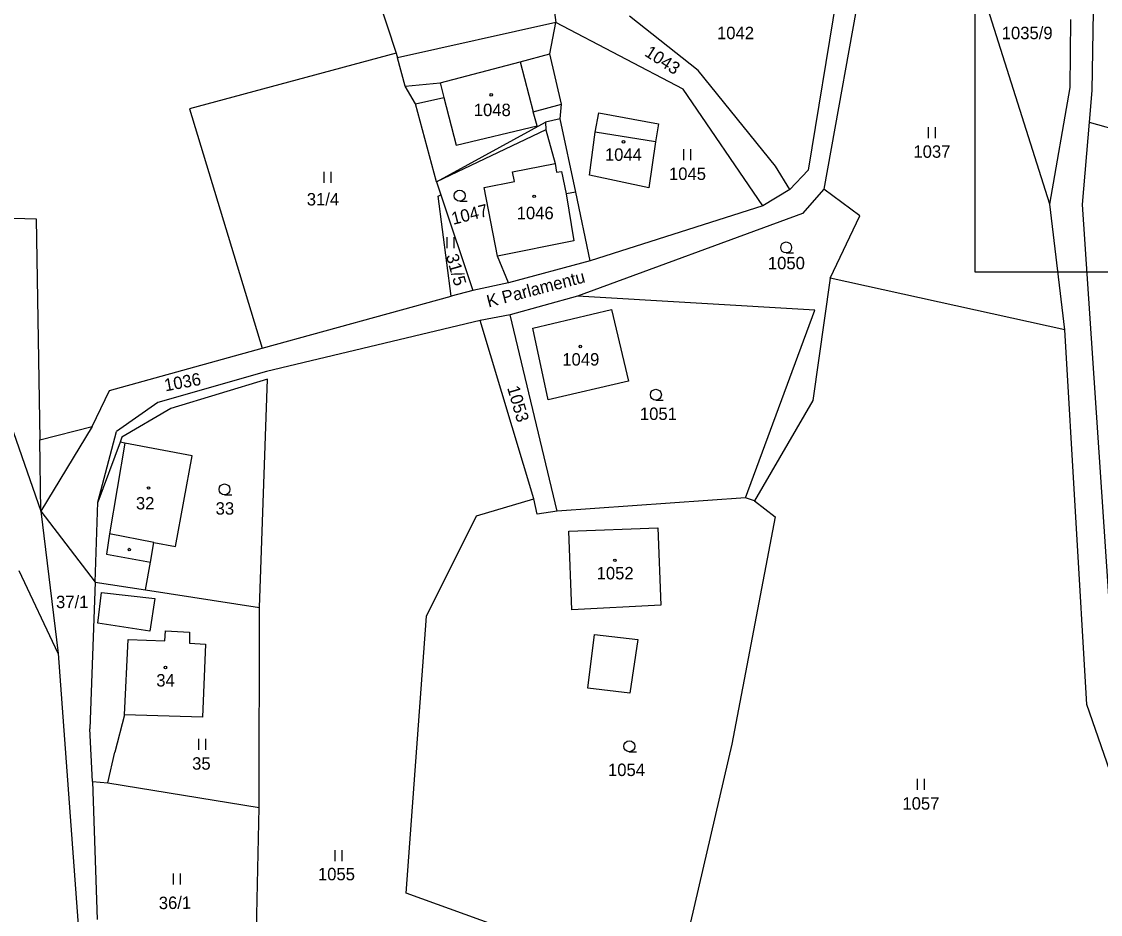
# Model space of a CAD drawing. Extents: x -670359 to -668019, y -978807 to -976674.
# Drawn here: x -670130.3 to -669982.9, y -977587.7 to -977465.8 of the extents above; entities that cross this region are included whole.
import ezdxf

# ---------------------------------------------------------------- set-up
doc = ezdxf.new("R2010")
doc.units = 0
for name, color, linetype in [('Hranice parcel', 7, 'Continuous'), ('ML1000', 7, 'Continuous'), ('Parcelní čísla', 7, 'Continuous'), ('Pop  PČ popisy', 7, 'Continuous'), ('Vnitřní kresba', 7, 'Continuous'), ('Značky budov', 7, 'Continuous'), ('Značky kultur', 7, 'Continuous')]:
    doc.layers.add(name, color=color, linetype=linetype)

msp = doc.modelspace()

# ---------------------------------------------------------------- linework, layer by layer
at = {"layer": 'Hranice parcel'}
for p, q in [((-670088.14, -977442.36), (-670079.11, -977470.1)), ((-670018.36, -977458.79), (-670022.83, -977486.05)), ((-669983.91, -977464.41), (-669984.06, -977475.2)), ((-669987.06, -977474.79), (-669986.93, -977465.5)), ((-669989.82, -977490.72), (-669987.06, -977474.79)), ((-669984.06, -977475.2), (-669984.43, -977479.49)), ((-669984.43, -977479.49), (-669985.41, -977490.75)), ((-669984.43, -977479.49), (-669976.06, -977481.88)), ((-670073, -977489.41), (-670068.64, -977502.48)), ((-670068.64, -977502.48), (-670071.6, -977503.29))]:
    msp.add_line(p, q, dxfattribs=at)
for points in [[(-670059.08, -977452.8), (-670057.31, -977465.91)], [(-670015.27, -977458.55), (-670020.69, -977488.66)], [(-669989.82, -977490.72), (-669999.13, -977461.22)], [(-670057.31, -977465.91), (-670078.9, -977470.74)], [(-670058.09, -977470.17), (-670057.31, -977465.91)], [(-670039.88, -977475.01), (-670057.31, -977465.91)], [(-670037.86, -977472.47), (-670047.21, -977465.04)], [(-670079.11, -977470.1), (-670107.35, -977477.66), (-670097.41, -977510.39)], [(-670079.11, -977470.1), (-670078.9, -977470.74)], [(-670077.89, -977474.59), (-670078.9, -977470.74)], [(-670056.54, -977477.05), (-670058.09, -977470.17)], [(-670027.27, -977485.52), (-670037.86, -977472.47)], [(-670076.46, -977477), (-670077.89, -977474.59)], [(-670029.03, -977490.92), (-670039.88, -977475.01)], [(-670073.58, -977487.65), (-670076.46, -977477)], [(-670056.71, -977479.05), (-670056.54, -977477.05)], [(-670073.58, -977487.65), (-670058.72, -977479.52)], [(-670056.71, -977479.05), (-670058.72, -977479.52)], [(-670058.72, -977479.52), (-670058.64, -977480.56)], [(-670054.54, -977489.07), (-670056.71, -977479.05)], [(-670051.92, -977480.85), (-670051.42, -977478.21)], [(-670051.42, -977478.21), (-670043.27, -977479.71)], [(-670058.64, -977480.56), (-670057.4, -977485.14)], [(-670052.69, -977486.76), (-670051.92, -977480.85)], [(-670043.27, -977479.71), (-670043.69, -977482.18)], [(-670043.69, -977482.18), (-670044.6, -977488.45)], [(-670063.22, -977486.29), (-670057.4, -977485.14)], [(-670025.33, -977488.71), (-670027.27, -977485.52)], [(-670062.96, -977487.6), (-670063.22, -977486.29)], [(-670044.6, -977488.45), (-670052.69, -977486.76)], [(-670022.83, -977486.05), (-670025.33, -977488.71)], [(-670073.58, -977487.65), (-670073, -977489.41)], [(-670067.1, -977488.42), (-670062.96, -977487.6)], [(-670065.25, -977497.79), (-670067.1, -977488.42)], [(-670071.6, -977503.29), (-670073.38, -977489.59), (-670073, -977489.41)], [(-670052.61, -977498.44), (-670054.54, -977489.07)], [(-670025.33, -977488.71), (-670029.03, -977490.92)], [(-670020.69, -977488.66), (-670023.59, -977492)], [(-670015.75, -977492.3), (-670020.69, -977488.66)], [(-670029.03, -977490.92), (-670052.61, -977498.44)], [(-669987.78, -977507.85), (-669989.82, -977490.72)], [(-669985.41, -977490.75), (-669980.86, -977558.44)], [(-670142.11, -977492.29), (-670128.27, -977492.71)], [(-670128.27, -977492.71), (-670127.79, -977522.9)], [(-670023.59, -977492), (-670054.32, -977503.26)], [(-670019.82, -977500.82), (-670015.75, -977492.3)], [(-670063.75, -977501.44), (-670065.25, -977497.79)], [(-670052.61, -977498.44), (-670063.75, -977501.44)], [(-670063.75, -977501.44), (-670068.64, -977502.48)], [(-670019.82, -977500.82), (-670022.18, -977517.52)], [(-669987.78, -977507.85), (-670019.82, -977500.82)], [(-670097.41, -977510.39), (-670071.6, -977503.29)], [(-670054.32, -977503.26), (-670063.55, -977505.8)], [(-670021.93, -977505.17), (-670054.32, -977503.26)], [(-670063.55, -977505.8), (-670067.63, -977506.57)], [(-670057.1, -977532.64), (-670063.55, -977505.8)], [(-670060.44, -977507.66), (-670049.7, -977505.09)], [(-670049.7, -977505.09), (-670047.37, -977514.87)], [(-670031.38, -977530.79), (-670021.93, -977505.17)], [(-670067.63, -977506.57), (-670096.81, -977513.56)], [(-670060.28, -977530.93), (-670067.63, -977506.57)], [(-670136.3, -977507.85), (-670127.64, -977532.62)], [(-670058.35, -977517.43), (-670060.44, -977507.66)], [(-669984.78, -977559.05), (-669987.78, -977507.85)], [(-670118.28, -977516.13), (-670097.41, -977510.39)], [(-670096.81, -977513.56), (-670111.65, -977517.78)], [(-670096.66, -977514.6), (-670109.89, -977518.59)], [(-670097.76, -977545.79), (-670096.66, -977514.6)], [(-670047.37, -977514.87), (-670058.35, -977517.43)], [(-670120.63, -977521.08), (-670118.28, -977516.13)], [(-670111.65, -977517.78), (-670117.28, -977521.74)], [(-670022.18, -977517.52), (-670030.15, -977531.24)], [(-670109.89, -977518.59), (-670116.56, -977522.54)], [(-670127.79, -977522.9), (-670120.63, -977521.08)], [(-670119.83, -977531.4), (-670117.28, -977521.74)], [(-670127.64, -977532.62), (-670127.79, -977522.9)], [(-670116.81, -977523.22), (-670119.83, -977531.4)], [(-670116.56, -977522.54), (-670116.81, -977523.22)], [(-670116.17, -977523.35), (-670116.81, -977523.22)], [(-670106.98, -977525.09), (-670116.17, -977523.35)], [(-670109.23, -977537.47), (-670106.98, -977525.09)], [(-670068.14, -977533.28), (-670060.28, -977530.93)], [(-670059.82, -977533.02), (-670060.28, -977530.93)], [(-670031.38, -977530.79), (-670057.1, -977532.64)], [(-670030.15, -977531.24), (-670031.38, -977530.79)], [(-670127.64, -977532.62), (-670125.26, -977552.07)], [(-670127.64, -977532.62), (-670120.22, -977542.35)], [(-670120.22, -977542.35), (-670119.83, -977531.4)], [(-670057.1, -977532.64), (-670059.82, -977533.02)], [(-670030.15, -977531.24), (-670027.32, -977533.4)], [(-670074.96, -977546.99), (-670068.14, -977533.28)], [(-670027.32, -977533.4), (-670033.24, -977564.47)], [(-670055.52, -977535.37), (-670043.35, -977534.89)], [(-670055.11, -977546.09), (-670055.52, -977535.37)], [(-670043.35, -977534.89), (-670042.94, -977545.45)], [(-670112.68, -977539.61), (-670112.18, -977536.89)], [(-670112.18, -977536.89), (-670109.23, -977537.47)], [(-670113.35, -977543.36), (-670112.68, -977539.61)], [(-670125.26, -977552.07), (-670130.59, -977540.77)], [(-670120.22, -977542.35), (-670120.93, -977562.34)], [(-670120.22, -977542.35), (-670113.35, -977543.36)], [(-670113.35, -977543.36), (-670097.76, -977545.79)], [(-670097.83, -977573.12), (-670097.76, -977545.79)], [(-670042.94, -977545.45), (-670055.11, -977546.09)], [(-670077.72, -977584.8), (-670074.96, -977546.99)], [(-670116.19, -977560.46), (-670115.72, -977550.14)], [(-670115.72, -977550.14), (-670110.68, -977550.34)], [(-670110.68, -977550.34), (-670110.59, -977548.98)], [(-670110.59, -977548.98), (-670107.31, -977549.16)], [(-670107.31, -977549.16), (-670107.32, -977550.68)], [(-670107.32, -977550.68), (-670105.16, -977550.78)], [(-670105.16, -977550.78), (-670105.55, -977560.77)], [(-670125.26, -977552.07), (-670122.35, -977591.65)], [(-669964.98, -977616.04), (-669984.78, -977559.05)], [(-670105.55, -977560.77), (-670116.19, -977560.46)], [(-670120.58, -977569.54), (-670120.93, -977562.34)], [(-670033.24, -977564.47), (-670040.09, -977593.86)], [(-670120.58, -977569.54), (-670118.5, -977569.72)], [(-670120.58, -977569.54), (-670119.93, -977588.41)], [(-670118.5, -977569.72), (-670097.83, -977573.12)], [(-670098.33, -977596.16), (-670097.83, -977573.12)], [(-670057.34, -977592.2), (-670077.72, -977584.8)]]:
    msp.add_lwpolyline(points, dxfattribs=at)
at = {"layer": 'ML1000'}
msp.add_lwpolyline([(-669375, -977000), (-669375, -977500), (-670000, -977500), (-670000, -977000)], close=True, dxfattribs=at)
at = {"layer": 'Vnitřní kresba'}
for points in [[(-670062.18, -977471.26), (-670058.09, -977470.17)], [(-670073.08, -977474.14), (-670062.18, -977471.26)], [(-670062.18, -977471.26), (-670060.39, -977478.07)], [(-670077.89, -977474.59), (-670073.08, -977474.14)], [(-670073.08, -977474.14), (-670072.61, -977476.14)], [(-670076.46, -977477), (-670072.61, -977476.14)], [(-670072.61, -977476.14), (-670070.9, -977482.63)], [(-670060.39, -977478.07), (-670056.54, -977477.05)], [(-670059.84, -977479.99), (-670060.39, -977478.07)], [(-670058.64, -977480.56), (-670073.58, -977487.65)], [(-670070.9, -977482.63), (-670059.84, -977479.99)], [(-670043.69, -977482.18), (-670051.92, -977480.85)], [(-670057.4, -977485.14), (-670057.2, -977486.32)], [(-670057.2, -977486.32), (-670056.5, -977486.25)], [(-670056.5, -977486.25), (-670055.9, -977489.3)], [(-670054.54, -977489.07), (-670055.9, -977489.3)], [(-670055.9, -977489.3), (-670054.83, -977495.7)], [(-670054.83, -977495.7), (-670065.25, -977497.79)], [(-670120.63, -977521.08), (-670127.64, -977532.62)], [(-670116.17, -977523.35), (-670118.26, -977535.73)], [(-670118.26, -977535.73), (-670118.68, -977538.52)], [(-670112.18, -977536.89), (-670118.26, -977535.73)], [(-670118.68, -977538.52), (-670112.68, -977539.61)], [(-670119.86, -977547.95), (-670119.35, -977543.72)], [(-670119.35, -977543.72), (-670112.08, -977544.57)], [(-670112.08, -977544.57), (-670112.75, -977549.04)], [(-670112.75, -977549.04), (-670119.86, -977547.95)], [(-670052.9, -977556.8), (-670052.02, -977549.47)], [(-670052.02, -977549.47), (-670046.1, -977550.15)], [(-670046.1, -977550.15), (-670047.19, -977557.5)], [(-670047.19, -977557.5), (-670052.9, -977556.8)], [(-670116.19, -977560.46), (-670117.51, -977565.57)], [(-670118.5, -977569.72), (-670117.51, -977565.57)]]:
    msp.add_lwpolyline(points, dxfattribs=at)
at = {"layer": 'Značky budov'}
for centre in [(-670066.11, -977475.78), (-670048.05, -977482.18), (-670060.25, -977489.63), (-670053.95, -977510.15), (-670112.92, -977529.47), (-670049.22, -977539.35), (-670110.62, -977553.98)]:
    msp.add_circle(centre, 0.175, dxfattribs=at)
at = {"layer": 'Značky kultur'}
for p, q in [((-670006.45, -977480.17), (-670006.45, -977481.67)), ((-670005.45, -977481.67), (-670005.45, -977480.17)), ((-670039.84, -977483.2), (-670039.84, -977484.7)), ((-670038.84, -977484.7), (-670038.84, -977483.2)), ((-670089, -977486.27), (-670089, -977487.77)), ((-670088, -977487.77), (-670088, -977486.27)), ((-670070.42, -977490.3), (-670069.42, -977490.3)), ((-670072.19, -977495.21), (-670072.19, -977496.71)), ((-670071.19, -977496.71), (-670071.19, -977495.21)), ((-670025.83, -977497.37), (-670024.83, -977497.37)), ((-670043.63, -977517.48), (-670042.63, -977517.48)), ((-670102.55, -977530.41), (-670101.55, -977530.41)), ((-670106.1, -977563.72), (-670106.1, -977565.22)), ((-670105.1, -977565.22), (-670105.1, -977563.72)), ((-670047.26, -977565.49), (-670046.26, -977565.49)), ((-670007.95, -977569.2), (-670007.95, -977570.7)), ((-670006.95, -977570.7), (-670006.95, -977569.2)), ((-670087.47, -977578.94), (-670087.47, -977580.44)), ((-670086.47, -977580.44), (-670086.47, -977578.94)), ((-670109.56, -977582.1), (-670109.56, -977583.6)), ((-670108.56, -977583.6), (-670108.56, -977582.1))]:
    msp.add_line(p, q, dxfattribs=at)
for centre, radius in [((-670066.11, -977475.78), 0.175), ((-670048.05, -977482.18), 0.175), ((-670070.42, -977489.55), 0.75), ((-670060.25, -977489.63), 0.175), ((-670025.83, -977496.62), 0.75), ((-670053.95, -977510.15), 0.175), ((-670043.63, -977516.73), 0.75), ((-670112.92, -977529.47), 0.175), ((-670102.55, -977529.66), 0.75), ((-670115.55, -977537.88), 0.175), ((-670049.22, -977539.35), 0.175), ((-670110.62, -977553.98), 0.175), ((-670047.26, -977564.74), 0.75)]:
    msp.add_circle(centre, radius, dxfattribs=at)

# ---------------------------------------------------------------- texts
at = {"layer": 'Parcelní čísla'}
for s, p in [('1035/9', (-669996.39, -977468.17)), ('1042', (-670035.28, -977468.17)), ('1048', (-670068.5, -977478.68)), ('1044', (-670050.59, -977484.78)), ('1037', (-670008.45, -977484.37)), ('1045', (-670041.84, -977487.4)), ('31/4', (-670091.31, -977490.88)), ('1046', (-670062.64, -977492.76)), ('1050', (-670028.33, -977499.6)), ('1049', (-670056.41, -977512.75)), ('1051', (-670045.81, -977520.18)), ('32', (-670114.65, -977532.4)), ('33', (-670103.76, -977533.11)), ('1052', (-670051.72, -977541.95)), ('37/1', (-670125.56, -977545.88)), ('34', (-670111.87, -977556.58)), ('35', (-670106.97, -977567.94)), ('1054', (-670050.17, -977568.81)), ('1057', (-670009.95, -977573.4)), ('1055', (-670089.79, -977583.05))]:
    msp.add_text(s, height=1.7, dxfattribs=at).set_placement(p)
for s, rotation, p in [('1043', 327.0425, (-670045.29, -977470.35)), ('1047', 14.1423, (-670071.32, -977493.53)), ('31/5', 285.9416, (-670072.32, -977497.75)), ('1036', 10.3585, (-670110.62, -977516.28)), ('1053', 286.3649, (-670063.96, -977515.78)), ('36/1', 0.6585, (-670111.52, -977586.99))]:
    msp.add_text(s, height=1.7, rotation=rotation, dxfattribs=at).set_placement(p)
at = {"layer": 'Pop  PČ popisy'}
msp.add_text('K Parlamentu', height=1.7, rotation=14.6263, dxfattribs=at).set_placement((-670066.49, -977504.83))

doc.saveas('drawing.dxf')
